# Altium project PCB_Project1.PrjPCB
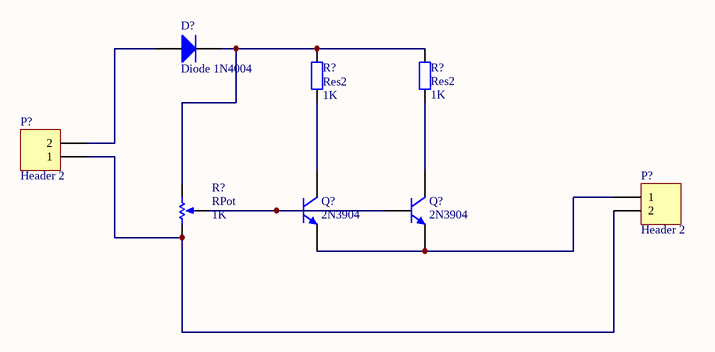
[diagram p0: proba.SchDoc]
1 sheet, 8 parts. Net scope: global (net labels, ports and power ports of the same name join across sheets).
Board file: proba.PcbDoc

## Sheet proba.SchDoc
size A; DrawnBy: djusee

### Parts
(Parts that share a designator on the sheet are numbered #1, #2 ... from top to bottom, then left to right.)
D?  Diode 1N4004  [DO-41]
P?#1  Header 2  [HDR1X2]
P?#2  Header 2  [HDR1X2]
Q?#1  2N3904  [TO-92A]
Q?#2  2N3904  [TO-92A]
R?#1  Res2  value 1K  [AXIAL-0.4]
R?#2  Res2  value 1K  [AXIAL-0.4]
R?#3  RPot  value 1K  [VR5]

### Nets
NetD?_1: D?.1(A) P?#1.2
NetD?_2: D?.2(K) R?#1.2 R?#2.2 R?#3.2(BOT)
NetP?#1_1: P?#1.1 P?#2.2 R?#3.1(TOP)
NetP?#2_1: P?#2.1 Q?#1.1(E) Q?#2.1(E)
NetQ?#1_2: Q?#1.2(B) Q?#2.2(B) R?#3.3(TAP)
NetQ?#1_3: Q?#1.3(C) R?#1.1
NetQ?#2_3: Q?#2.3(C) R?#2.1

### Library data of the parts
D? = Diode 1N4004: 1 Amp General Purpose Rectifier
P?#1 P?#2 = Header 2: Header, 2-Pin
Q?#1 Q?#2 = 2N3904: NPN General Purpose Amplifier
R?#1 R?#2 = Res2: Resistor
R?#3 = RPot: Potentiometer; Sim Note: Enter the Resistance value and the set point into parameter fields.; Set Position: 0.5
